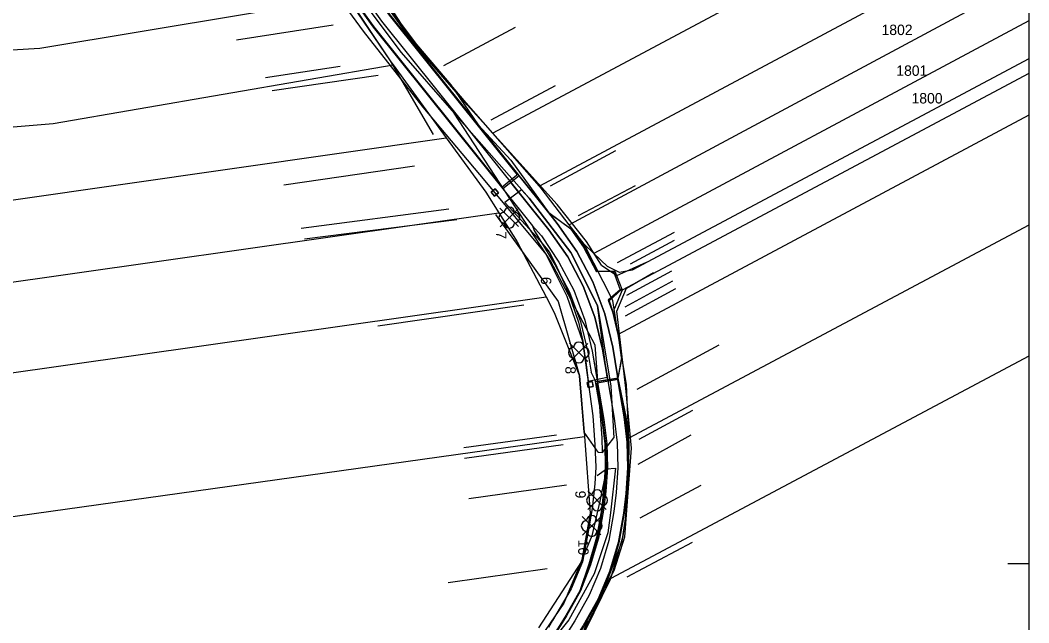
# Model space of a CAD drawing. Extents: x -601800 to -601487, y -1201912 to -1200862.
# Drawn here: x -601680 to -601486.7, y -1201083.7 to -1200968.1 of the extents above; entities that cross this region are included whole.
import ezdxf

# ---------------------------------------------------------------- set-up
doc = ezdxf.new("R2010")
doc.units = 0
for name, color, linetype in [('Hranice parcel', 7, 'Continuous'), ('Parcelní čísla', 7, 'Continuous'), ('popis', 7, 'Continuous'), ('u_hrany', 7, 'Continuous'), ('U_keř', 7, 'Continuous'), ('u_návrh', 7, 'Continuous'), ('u_osa', 7, 'Continuous'), ('u_strom', 7, 'Continuous'), ('u_terénní úpravy', 7, 'Continuous'), ('x_rám', 7, 'Continuous')]:
    doc.layers.add(name, color=color, linetype=linetype)

msp = doc.modelspace()

# ---------------------------------------------------------------- linework, layer by layer
at = {"layer": 'Hranice parcel'}
for p, q in [((-601486.66, -1200934.79), (-601589.41, -1200989.76)), ((-601486.66, -1200949.76), (-601580.47, -1200999.94)), ((-601486.66, -1200960.04), (-601574.8, -1201007.3)), ((-601486.66, -1200968.18), (-601570.05, -1201012.84)), ((-601608.55, -1200976.64), (-601598.35, -1200990.64)), ((-601580.47, -1200999.94), (-601589.41, -1200989.76)), ((-601571.94, -1201011.04), (-601574.8, -1201007.3)), ((-601570.05, -1201012.84), (-601571.94, -1201011.04)), ((-601565.38, -1201028.39), (-601566.18, -1201023.48))]:
    msp.add_line(p, q, dxfattribs=at)
for points in [[(-601783.66, -1200979.83), (-601676.3, -1200973.45), (-601617.41, -1200963.63)], [(-601617.41, -1200963.63), (-601609.12, -1200975.86), (-601608.55, -1200976.64)], [(-601589.41, -1200989.76), (-601594.55, -1200983.92), (-601604.39, -1200972.37), (-601611.28, -1200963.08)], [(-601486.66, -1200975.47), (-601562.69, -1201016.01), (-601565.17, -1201016.45), (-601567.43, -1201015.35), (-601570.05, -1201012.84)], [(-601783.66, -1200997.03), (-601673.71, -1200987.92), (-601608.55, -1200976.64)], [(-601486.66, -1200978.3), (-601564.64, -1201019.88), (-601566.18, -1201023.48)], [(-601486.66, -1200986.32), (-601565.38, -1201028.39)], [(-601783.66, -1201015.11), (-601764.33, -1201014.41), (-601598.35, -1200990.64)], [(-601598.35, -1200990.64), (-601590.76, -1201001.05), (-601588.26, -1201005.03)], [(-601574.8, -1201007.3), (-601580.14, -1201000.32), (-601580.47, -1200999.94)], [(-601783.66, -1201032.85), (-601702.41, -1201021.28), (-601588.26, -1201005.03)], [(-601588.26, -1201005.03), (-601584.77, -1201010.59), (-601579.23, -1201021.11)], [(-601486.66, -1201007.38), (-601563.36, -1201048.24)], [(-601566.18, -1201023.48), (-601566.45, -1201021.87), (-601571.94, -1201011.04)], [(-601783.66, -1201043.44), (-601762.66, -1201047.22), (-601579.23, -1201021.11)], [(-601579.23, -1201021.11), (-601577.64, -1201024.12), (-601572.78, -1201036.3), (-601571.88, -1201047.94)], [(-601563.36, -1201048.24), (-601563.8, -1201037.94), (-601565.38, -1201028.39)], [(-601486.66, -1201032.52), (-601566.81, -1201075.18)], [(-601783.66, -1201077.55), (-601782.86, -1201077.45), (-601677.38, -1201062.7), (-601571.88, -1201047.94)], [(-601571.88, -1201047.94), (-601570.74, -1201062.64), (-601572.44, -1201071.88), (-601580.66, -1201084.64)], [(-601566.81, -1201075.18), (-601564.41, -1201067.01), (-601563.85, -1201062.82), (-601563.26, -1201050.66), (-601563.36, -1201048.24)], [(-601576.81, -1201092.27), (-601571.6, -1201084.92), (-601566.85, -1201075.32), (-601566.81, -1201075.18)]]:
    msp.add_lwpolyline(points, dxfattribs=at)
at = {"layer": 'u_hrany'}
for points in [[(-601637.65, -1200892.44), (-601636.56, -1200901.01), (-601634.78, -1200919.25), (-601632.6, -1200928.32), (-601629.33, -1200937.82), (-601624.51, -1200947.91), (-601616.86, -1200961.13), (-601606.97, -1200974.25), (-601596.82, -1200985.88), (-601582.46, -1201002.22), (-601574.49, -1201012.64), (-601569.33, -1201022.81), (-601566.79, -1201038.25), (-601566.21, -1201048.21)], [(-601568.57, -1201015.08), (-601571.45, -1201010.54), (-601577.11, -1201003.42), (-601594.37, -1200984.29), (-601604.5, -1200972.6), (-601614.07, -1200959.31), (-601621.9, -1200946.57), (-601626.39, -1200937.08), (-601629.97, -1200926.48)], [(-601629.33, -1200937.82), (-601626.28, -1200948.41), (-601618.2, -1200962.23), (-601609.12, -1200975.86), (-601600.84, -1200990.01)], [(-601604.5, -1200972.6), (-601610.78, -1200962.81), (-601598.49, -1200956.19)], [(-601620.01, -1200969.04), (-601638.58, -1200971.89)], [(-601598.82, -1200976.74), (-601585.07, -1200969.44)], [(-601618.7, -1200976.96), (-601633.03, -1200979.15)], [(-601611.44, -1200978.7), (-601631.71, -1200981.63)], [(-601589.75, -1200987.22), (-601577.41, -1200980.62)], [(-601568.4, -1201051.01), (-601568.48, -1201048.17), (-601569.79, -1201030.44), (-601578.37, -1201014.24), (-601596.82, -1200985.88)], [(-601578.4, -1200999.82), (-601565.82, -1200993.09)], [(-601604.42, -1200996.09), (-601629.51, -1200999.7)], [(-601572.97, -1201005.53), (-601562.07, -1200999.78)], [(-601597.83, -1201004.3), (-601626.18, -1201008.06)], [(-601596.32, -1201006.38), (-601625.53, -1201010.1)], [(-601588.94, -1201005.38), (-601576.88, -1201022.04), (-601572.78, -1201036.3)], [(-601565.54, -1201014.55), (-601554.59, -1201008.71)], [(-601563.01, -1201014.78), (-601554.59, -1201010.3)], [(-601568.57, -1201015.08), (-601565.66, -1201017.05), (-601559.94, -1201014.5)], [(-601565.63, -1201023.86), (-601563.77, -1201019.45), (-601558.64, -1201016.46)], [(-601563.76, -1201020.81), (-601555.1, -1201016.14)], [(-601564.07, -1201023.05), (-601554.94, -1201018.09)], [(-601563.96, -1201024.78), (-601554.36, -1201019.56)], [(-601583.46, -1201022.72), (-601611.5, -1201026.74)], [(-601571.17, -1201082.7), (-601566.15, -1201073.64), (-601564.1, -1201067.16), (-601562.87, -1201050.17), (-601563.92, -1201038.63), (-601565.63, -1201023.86)], [(-601561.78, -1201038.84), (-601546.05, -1201030.33)], [(-601569.26, -1201050.91), (-601571.94, -1201047.12), (-601572.78, -1201036.3)], [(-601561.39, -1201048.45), (-601551.08, -1201042.85)], [(-601577.2, -1201047.67), (-601595, -1201050.11)], [(-601561.59, -1201053.25), (-601551.43, -1201047.62)], [(-601575.95, -1201049.52), (-601594.84, -1201052.15)], [(-601568.4, -1201051.01), (-601566.21, -1201048.21)], [(-601569.26, -1201050.91), (-601568.4, -1201051.01)], [(-601567.64, -1201054.11), (-601568.91, -1201060.36), (-601570.43, -1201066.96), (-601575.8, -1201079.91), (-601579.37, -1201085.15), (-601582.23, -1201090.92), (-601591.68, -1201101.99), (-601597.36, -1201109.27), (-601610.21, -1201123.79), (-601614.29, -1201128.53), (-601618.14, -1201134.51), (-601624.79, -1201147.13)], [(-601565.88, -1201054.02), (-601566.84, -1201062.55), (-601567.35, -1201066.39), (-601569.99, -1201074.28), (-601574.88, -1201083.12), (-601587.13, -1201098.35), (-601606.12, -1201120.23), (-601612.39, -1201128.07), (-601618.22, -1201138.07), (-601622.89, -1201146.38)], [(-601569.4, -1201055.4), (-601567.64, -1201054.11), (-601565.88, -1201054.02)], [(-601575.32, -1201057.27), (-601594.05, -1201059.86)], [(-601561.16, -1201063.54), (-601549.49, -1201057.29)], [(-601563.65, -1201074.84), (-601551.12, -1201068.22)], [(-601579.04, -1201073.34), (-601598, -1201076.01)], [(-601574.23, -1201092.29), (-601571.17, -1201082.7)]]:
    msp.add_lwpolyline(points, dxfattribs=at)
at = {"layer": 'U_keř'}
for p, q in [((-601588.06, -1201004.14), (-601584.52, -1201007.67)), ((-601584.48, -1201004.17), (-601588.02, -1201007.71)), ((-601574.75, -1201030.02), (-601571.21, -1201033.56)), ((-601571.18, -1201030.06), (-601574.71, -1201033.59)), ((-601571.24, -1201058.37), (-601567.7, -1201061.9)), ((-601567.67, -1201058.4), (-601571.2, -1201061.94)), ((-601572.27, -1201063.28), (-601568.74, -1201066.82)), ((-601568.7, -1201063.32), (-601572.24, -1201066.85))]:
    msp.add_line(p, q, dxfattribs=at)
msp.add_lwpolyline([(-601583.9, -1201000.59), (-601587.13, -1201003.05), (-601580.81, -1201009.87), (-601578.62, -1201012.5), (-601577.47, -1201014.76), (-601575.02, -1201020.08), (-601573.02, -1201025.97), (-601572.15, -1201029.65), (-601571.13, -1201037.33), (-601567.49, -1201036.53), (-601569.33, -1201022.81), (-601574.49, -1201012.64), (-601582.46, -1201002.22)], close=True, dxfattribs=at)
msp.add_lwpolyline([(-601571.73, -1201032.8), (-601571.69, -1201033.08), (-601571.13, -1201037.33), (-601567.49, -1201036.53), (-601569.33, -1201022.81), (-601574.49, -1201012.64), (-601582.46, -1201002.22), (-601583.9, -1201000.59), (-601587.13, -1201003.05), (-601580.81, -1201009.87), (-601578.62, -1201012.5), (-601577.47, -1201014.76), (-601575.02, -1201020.08), (-601573.02, -1201025.97), (-601572.15, -1201029.65), (-601572.05, -1201030.38)], dxfattribs=at)
for centre, start, end in [((-601572.94, -1201030.83), 0, 26.7584), ((-601571.94, -1201031.83), 282.3491, 90)]:
    msp.add_arc(centre, 1, start, end, dxfattribs=at)
at = {"layer": 'u_návrh'}
for p, q in [((-601574.48, -1201008.16), (-601578.72, -1201005.02)), ((-601581.83, -1201007.54), (-601581.51, -1201008.42)), ((-601566.3, -1201016.29), (-601569.57, -1201016.32)), ((-601566.02, -1201016.19), (-601566.3, -1201016.29)), ((-601564.99, -1201019.8), (-601567.32, -1201021.8)), ((-601564.71, -1201019.69), (-601564.99, -1201019.8)), ((-601564.73, -1201032.76), (-601565.23, -1201029.47)), ((-601564.73, -1201032.76), (-601565.43, -1201036.71)), ((-601569.85, -1201036.98), (-601570.59, -1201035.59)), ((-601565.43, -1201036.71), (-601569.77, -1201037.45)), ((-601565.38, -1201037.01), (-601569.72, -1201037.75))]:
    msp.add_line(p, q, dxfattribs=at)
for points in [[(-601637.84, -1200888.06), (-601633.99, -1200918.4), (-601631.97, -1200929.41), (-601628.75, -1200940.18), (-601624.36, -1200950.53), (-601618.86, -1200960.34), (-601612.36, -1200969.44), (-601581.83, -1201007.54)], [(-601637.7, -1200888.04), (-601633.84, -1200918.38), (-601631.83, -1200929.37), (-601628.61, -1200940.13), (-601624.22, -1200950.47), (-601618.73, -1200960.26), (-601612.24, -1200969.35), (-601587.62, -1201000.08)], [(-601634.02, -1200887.58), (-601630.18, -1200917.81), (-601628.22, -1200928.51), (-601625.12, -1200938.87), (-601620.9, -1200948.83), (-601615.61, -1200958.27), (-601609.28, -1200967.12), (-601584.73, -1200997.76)], [(-601633.88, -1200887.56), (-601630.04, -1200917.79), (-601628.08, -1200928.47), (-601624.98, -1200938.82), (-601620.76, -1200948.77), (-601615.48, -1200958.19), (-601609.16, -1200967.03), (-601578.72, -1201005.02)], [(-601584.61, -1200997.67), (-601586.17, -1200998.92), (-601587.73, -1201000.17)], [(-601584.4, -1200997.94), (-601585.96, -1200999.19), (-601587.52, -1201000.44)], [(-601569.37, -1201037.38), (-601567.4, -1201037.05), (-601568.4, -1201031.17), (-601569.85, -1201025.01), (-601572.08, -1201019.07), (-601575.03, -1201013.47), (-601578.67, -1201008.28), (-601585.96, -1200999.19), (-601587.52, -1201000.44), (-601581.83, -1201007.54), (-601581.33, -1201008.1), (-601580.12, -1201009.44), (-601576.74, -1201014.51), (-601573.9, -1201019.89), (-601571.77, -1201025.59), (-601570.36, -1201031.57), (-601569.37, -1201037.38)], [(-601567.4, -1201037.05), (-601565.43, -1201036.71), (-601565.5, -1201036.27), (-601566.44, -1201030.78), (-601567.94, -1201024.42), (-601570.25, -1201018.25), (-601573.32, -1201012.42), (-601577.07, -1201007.08), (-601578.72, -1201005.02), (-601584.4, -1200997.94), (-601585.96, -1200999.19), (-601578.67, -1201008.28), (-601575.03, -1201013.47), (-601572.08, -1201019.07), (-601569.85, -1201025.01), (-601568.4, -1201031.17), (-601567.4, -1201037.05)], [(-601588.66, -1201000.8), (-601588.98, -1201000.41), (-601589.75, -1201001.05), (-601589.11, -1201001.82), (-601588.34, -1201001.18), (-601588.66, -1201000.8)], [(-601578.72, -1201005.02), (-601577.07, -1201007.08), (-601573.32, -1201012.42), (-601570.25, -1201018.25), (-601567.94, -1201024.42), (-601566.44, -1201030.78), (-601565.5, -1201036.27)], [(-601581.83, -1201007.54), (-601580.12, -1201009.44), (-601576.74, -1201014.51), (-601573.9, -1201019.89), (-601571.77, -1201025.59), (-601570.36, -1201031.57), (-601568.13, -1201044.7), (-601567.57, -1201049.29), (-601567.46, -1201053.88), (-601567.78, -1201058.5), (-601568.21, -1201062.05), (-601569.15, -1201067.4), (-601570.67, -1201072.55), (-601572.61, -1201077.56)], [(-601581.51, -1201008.42), (-601577.52, -1201014.97), (-601574.73, -1201020.26), (-601572.63, -1201025.85), (-601571.24, -1201031.75), (-601570.59, -1201035.59)], [(-601574.48, -1201008.16), (-601572.04, -1201011.64), (-601569.57, -1201016.32)], [(-601566.3, -1201016.29), (-601564.99, -1201019.8)], [(-601566.02, -1201016.19), (-601564.71, -1201019.69)], [(-601567.32, -1201021.8), (-601566.5, -1201023.99), (-601565.23, -1201029.47)], [(-601565.53, -1201037.03), (-601564.32, -1201044.14), (-601563.73, -1201049.01), (-601563.6, -1201053.96), (-601563.95, -1201058.86), (-601564.4, -1201062.61), (-601565.39, -1201068.28), (-601567.03, -1201073.84), (-601569.28, -1201079.19), (-601572.09, -1201084.21), (-601573.68, -1201086.7), (-601576.62, -1201091.08), (-601579.81, -1201095.32), (-601583.19, -1201099.37), (-601602.51, -1201121.29), (-601608.95, -1201129.42), (-601614.47, -1201138.14), (-601619.05, -1201147.4), (-601622.65, -1201157.12), (-601623.73, -1201160.61)], [(-601565.43, -1201036.71), (-601564.17, -1201044.12), (-601563.58, -1201049), (-601563.45, -1201053.97), (-601563.8, -1201058.87), (-601564.25, -1201062.63), (-601565.25, -1201068.31), (-601566.89, -1201073.89), (-601569.15, -1201079.26), (-601571.96, -1201084.29), (-601573.55, -1201086.79), (-601576.5, -1201091.17), (-601579.69, -1201095.42), (-601583.08, -1201099.47), (-601602.4, -1201121.39), (-601608.83, -1201129.51), (-601614.34, -1201138.22), (-601618.91, -1201147.46), (-601622.51, -1201157.17), (-601623.59, -1201160.65)], [(-601569.85, -1201036.98), (-601568.53, -1201044.75), (-601567.97, -1201049.32), (-601567.86, -1201053.87), (-601568.18, -1201058.46), (-601568.6, -1201061.99), (-601569.54, -1201067.3), (-601571.04, -1201072.41), (-601572.75, -1201077.5)], [(-601569.57, -1201037.72), (-601568.38, -1201044.73), (-601567.82, -1201049.31), (-601567.71, -1201053.87), (-601568.03, -1201058.47), (-601568.45, -1201062.02), (-601569.39, -1201067.34), (-601570.9, -1201072.46), (-601572.61, -1201077.56)], [(-601570.27, -1201037.88), (-601570.36, -1201037.39), (-601571.35, -1201037.57), (-601571.16, -1201038.55), (-601570.18, -1201038.37), (-601570.27, -1201037.88)], [(-601572.75, -1201077.5), (-601575.4, -1201082.24), (-601576.9, -1201084.6), (-601579.76, -1201088.85), (-601582.83, -1201092.93), (-601586.12, -1201096.86), (-601605.47, -1201118.82), (-601612.1, -1201127.19), (-601617.84, -1201136.26), (-601622.59, -1201145.87), (-601626.29, -1201155.88), (-601627.44, -1201159.58), (-601628.96, -1201165.79), (-601629.7, -1201172.21), (-601629.64, -1201178.67), (-601628.79, -1201185.01), (-601625.54, -1201201.39), (-601623.73, -1201208.12), (-601620.99, -1201214.62), (-601617.4, -1201220.68), (-601613.06, -1201226.15), (-601607.6, -1201232.16), (-601599.98, -1201239.49)], [(-601572.61, -1201077.56), (-601575.27, -1201082.31), (-601576.77, -1201084.68), (-601579.64, -1201088.94), (-601582.71, -1201093.02), (-601586, -1201096.96), (-601605.35, -1201118.92), (-601611.97, -1201127.28), (-601617.7, -1201136.33), (-601622.45, -1201145.93), (-601626.15, -1201155.93), (-601627.3, -1201159.62), (-601628.81, -1201165.82), (-601629.55, -1201172.22), (-601629.49, -1201178.66), (-601628.64, -1201184.99), (-601625.4, -1201201.35), (-601623.58, -1201208.08), (-601620.85, -1201214.55), (-601617.27, -1201220.6), (-601612.94, -1201226.05), (-601607.49, -1201232.05), (-601599.86, -1201239.4)]]:
    msp.add_lwpolyline(points, dxfattribs=at)
for points in [[(-601588.98, -1201000.41), (-601588.34, -1201001.18), (-601589.11, -1201001.82), (-601589.75, -1201001.05)], [(-601570.36, -1201037.39), (-601570.18, -1201038.37), (-601571.16, -1201038.55), (-601571.35, -1201037.57)]]:
    msp.add_lwpolyline(points, close=True, dxfattribs=at)
at = {"layer": 'u_osa'}
msp.add_lwpolyline([(-601635.86, -1200887.81), (-601632.01, -1200918.1), (-601630.03, -1200928.94), (-601626.86, -1200939.5), (-601622.56, -1200949.65), (-601617.17, -1200959.27), (-601610.76, -1200968.24), (-601578.67, -1201008.28), (-601575.03, -1201013.47), (-601572.08, -1201019.07), (-601569.85, -1201025.01), (-601568.4, -1201031.17), (-601566.15, -1201044.41), (-601565.58, -1201049.15), (-601565.46, -1201053.92), (-601565.79, -1201058.68), (-601566.23, -1201062.34), (-601567.2, -1201067.85), (-601568.78, -1201073.22), (-601570.95, -1201078.38), (-601573.68, -1201083.26), (-601575.23, -1201085.69)], dxfattribs=at)
at = {"layer": 'u_strom'}
for centre in [(-601586.25, -1201005.94), (-601572.94, -1201031.83), (-601569.44, -1201060.17), (-601570.47, -1201065.09)]:
    msp.add_circle(centre, 0.1, dxfattribs=at)
for centre, start, end in [((-601587.25, -1201005.94), 90, 270), ((-601586.25, -1201004.94), 0, 180), ((-601585.25, -1201005.94), 270, 90), ((-601586.25, -1201006.94), 180, 0), ((-601572.94, -1201030.83), 0, 180), ((-601573.94, -1201031.83), 90, 270), ((-601571.94, -1201031.83), 270, 90), ((-601572.94, -1201032.83), 180, 0), ((-601570.44, -1201060.17), 90, 270), ((-601569.44, -1201059.17), 0, 180), ((-601568.44, -1201060.17), 270, 90), ((-601569.44, -1201061.17), 180, 0), ((-601570.47, -1201064.09), 0, 180), ((-601571.47, -1201065.09), 90, 270), ((-601569.47, -1201065.09), 270, 90), ((-601570.47, -1201066.09), 180, 0)]:
    msp.add_arc(centre, 1, start, end, dxfattribs=at)
at = {"layer": 'u_terénní úpravy'}
for points in [[(-601638.58, -1200888.16), (-601634.49, -1200918.5), (-601632.61, -1200929.56), (-601631.64, -1200933.52), (-601630.13, -1200940.76), (-601625.44, -1200954.33), (-601625.44, -1200954.33), (-601620.62, -1200961.46), (-601614.29, -1200970.18), (-601602.86, -1200984.78), (-601590.97, -1200998.92), (-601579.26, -1201012.94), (-601575.24, -1201021.04), (-601572.22, -1201029.67), (-601570.25, -1201043.99), (-601569.84, -1201049.5), (-601569.66, -1201053.83), (-601569.88, -1201056.99), (-601570.38, -1201061.73), (-601571.23, -1201066.55), (-601572.22, -1201071.99), (-601574.43, -1201077.13), (-601577.98, -1201083.22), (-601578.77, -1201084.58)], [(-601623.65, -1200937.04), (-601622.86, -1200939.89), (-601618.94, -1200950.91), (-601615.27, -1200957.89), (-601609.08, -1200966.05), (-601604.07, -1200972.75), (-601597.48, -1200980.48), (-601592.22, -1200988.18), (-601585.96, -1200994.9), (-601578.72, -1201005.02), (-601574.41, -1201008.09), (-601573.52, -1201008.97), (-601571.74, -1201011.84), (-601569.51, -1201016.17), (-601566.02, -1201016.19)], [(-601564.71, -1201019.69), (-601567.13, -1201021.89), (-601566.39, -1201023.99), (-601565.41, -1201028.19), (-601565.2, -1201029.48), (-601564.69, -1201032.75), (-601565.43, -1201036.71), (-601563.92, -1201044.08), (-601563.33, -1201049.03), (-601563.42, -1201053.97), (-601563.7, -1201058.88), (-601564.06, -1201063.72), (-601564.71, -1201068.03), (-601566.89, -1201073.89), (-601568.96, -1201079.35), (-601571.8, -1201084.68)]]:
    msp.add_lwpolyline(points, dxfattribs=at)
at = {"layer": 'x_rám'}
msp.add_line((-601486.66, -1201072.35), (-601490.7, -1201072.35), dxfattribs=at)
msp.add_lwpolyline([(-601486.66, -1200862.35), (-601486.66, -1201912.35), (-601783.66, -1201912.35), (-601783.66, -1200862.35)], close=True, dxfattribs=at)

# ---------------------------------------------------------------- texts
at = {"layer": 'Parcelní čísla'}
for s, p in [('1802', (-601514.9, -1200970.93)), ('1801', (-601512.07, -1200978.75)), ('1800', (-601509.15, -1200984.05))]:
    msp.add_text(s, height=2, dxfattribs=at).set_placement(p)
at = {"layer": 'popis'}
for s, p in [('7', (-601588.84, -1201008.58)), ('6', (-601580.21, -1201017.32)), ('8', (-601575.53, -1201034.47)), ('9', (-601573.61, -1201058.31)), ('10', (-601573.06, -1201067.73))]:
    msp.add_text(s, height=2, rotation=270, dxfattribs=at).set_placement(p)

doc.saveas('drawing.dxf')
